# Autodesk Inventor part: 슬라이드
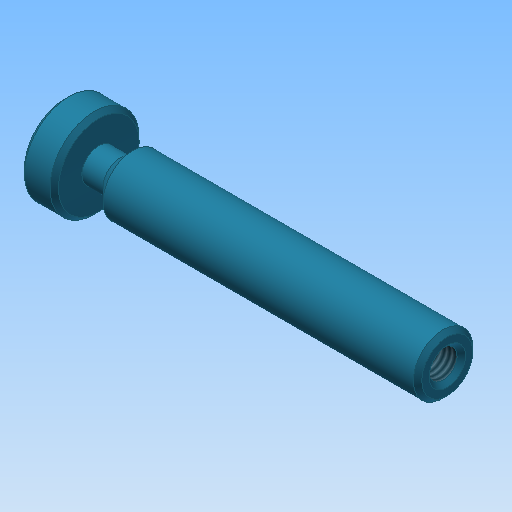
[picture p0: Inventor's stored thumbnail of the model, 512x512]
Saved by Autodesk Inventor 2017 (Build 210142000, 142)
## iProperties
Created: 2015-12
Part Number: 슬라이드
Document SubType Name: Modeling
Designer: mdu
Density: 8.08 g/cm^3
Material: 스테인리스강
Appearance: 터키옥색
Mass: 114.493 g
Surface Area: 49.8963 cm^2
Volume: 14.17 cm^3
Author: mdu
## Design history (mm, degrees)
sketch "스케치1"
  geometry: L1 (-45, 0)-(45, 0); L2 (-45, 0)-(-45, 10.5); L3 (-45, 10.5)-(-37, 10.5); L4 (-37, 10.5)-(-37, 4); L5 (-37, 4)-(-32, 4); L6 (-32, 4)-(-29, 7); L7 (-29, 7)-(45, 7); L8 (45, 7)-(45, 0); 2 further points
  constraints: 16 end point, 4 parallel, 2 perpendicular, 1 coincident, 1 horizontal, 1 midpoint
  dimensions: "d0" = 90 distance of L1.start L1.end; "d1" = 21 diameter of L3 L1; "d2" = 14 diameter of L7 L1; "d3" = 8 diameter of L5 L1; "d4" = 8 distance of L2.end L3.end; "d5" = 5 distance of L4.end L5.end; "d6" = 135 deg angle of L6 L5
revolve "회전1" sketch "스케치1" stored, may be unused: angle "d7" = 90 deg
chamfer "모따기1" distance "d8" = 1; stored, may be unused: second distance "d9" = 2, angle "d10" = 45 deg
hole "구멍1" diameter "d13" = 6.647; stored, may be unused: countersink angle "d17" = 90 deg, drill point angle "d19" = 118 deg; dims "d11" = 10, "d12" = 10, "d14" = 9, "d15" = 4, "d16" = 2, "d18" = 12
chamfer "모따기2" distance "d20" = 1; stored, may be unused: second distance "d21" = 2, angle "d22" = 45 deg
node "솔리드1"
